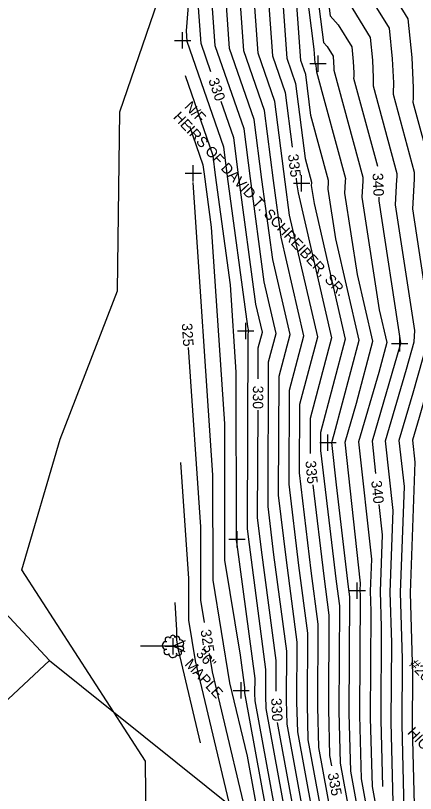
# Model space of a CAD drawing. Extents: x 487096 to 489566, y 221939 to 224454.
# Drawn here: x 488250.6 to 488373.2, y 222981.8 to 223219.9 of the extents above; entities that cross this region are included whole.
import ezdxf

# ---------------------------------------------------------------- set-up
doc = ezdxf.new("R2010")
doc.units = 0
for name, color, linetype in [('SV_CTRL_BM_INFO_BOX', 7, 'Continuous'), ('SV_ROWL_ROWL_TX', 7, 'Continuous'), ('SV_SURF_INDEX_CONTOUR', 7, 'Continuous'), ('SV_SURF_INTER_CONTOUR', 7, 'Continuous'), ('SV_SURF_SPOT', 7, 'Continuous'), ('SV_TREE_TREEVEG', 7, 'Continuous'), ('SV_TREE_TREEVEG_TX', 7, 'Continuous'), ('SV_UTOH_MISC_OH', 7, 'Continuous'), ('SV_UTOH_UTOH_TX', 7, 'Continuous'), ('SV_WATR_INWETF', 7, 'Continuous')]:
    doc.layers.add(name, color=color, linetype=linetype)

msp = doc.modelspace()

# ---------------------------------------------------------------- linework, layer by layer
at = {"layer": 'SV_CTRL_BM_INFO_BOX'}
msp.add_line((488260.98, 223022.49), (488394.91, 222915.38), dxfattribs=at)
msp.add_lwpolyline([(488175.2, 223114.48), (488260.98, 223022.49), (488234.03, 222997.36), (488148.26, 223089.35)], close=True, dxfattribs=at)
at = {"layer": 'SV_SURF_INDEX_CONTOUR'}
for points in [[(488310.47, 223202.71), (488307.47, 223211.35), (488306.48, 223225.22), (488310.84, 223279.98), (488309.25, 223288.25)], [(488325.23, 223265.13), (488329.34, 223207.61), (488333.25, 223196.36), (488335.38, 223179.67)], [(488342.28, 223256.77), (488347.01, 223219.79), (488349.5, 223217.08), (488353.65, 223210.35), (488354.1, 223205.9), (488354.27, 223202.43), (488354.27, 223202.11), (488354.27, 223201.89), (488354.26, 223201.45), (488354.26, 223201.23), (488354.25, 223200.78), (488361.53, 223173.86)], [(488324.97, 223108.74), (488325.01, 223118.17), (488326.28, 223122.95), (488324.29, 223131.57), (488319.04, 223170.36), (488317.49, 223182.52), (488313.62, 223193.65)], [(488336.6, 223170.15), (488336.78, 223168.73), (488337.2, 223165.67), (488347.45, 223121.22), (488340.91, 223096.6), (488340.87, 223085.82)], [(488361.98, 223164.27), (488361.92, 223163.16), (488368.63, 223119.72), (488368.62, 223119.55), (488368.5, 223119.11), (488359.9, 223089.58), (488360.97, 223079.74)], [(488308.53, 223034.09), (488307.4, 223040.95), (488307.36, 223063.37), (488303.66, 223118.32)], [(488330.45, 223013.12), (488330.49, 223022.52), (488325.99, 223056.4), (488324.81, 223066.24), (488324.94, 223099.14)], [(488341.7, 223076.26), (488345.07, 223048.28), (488346.65, 223036.4), (488346.5, 223007.64), (488346.86, 222993.42), (488347.45, 222990.23)], [(488362.01, 223070.2), (488363.02, 223060.95), (488362.4, 223043.57), (488362.71, 223032.73), (488362.56, 223004.23), (488363.08, 222983.89)], [(488328.45, 222940.22), (488324.17, 222963.52), (488311, 223019), (488310.08, 223024.61)], [(488344.86, 222918.34), (488344.39, 222924.14), (488343.22, 222936.46), (488330.92, 223003.53)]]:
    msp.add_lwpolyline(points, dxfattribs=at)
at = {"layer": 'SV_SURF_INTER_CONTOUR'}
for points in [[(488308.1, 223280.91), (488302.87, 223215.26), (488303.09, 223212.1), (488314.33, 223179.75), (488315.49, 223170.68), (488321.71, 223124.75), (488322.05, 223123.29), (488321.83, 223122.48), (488321.6, 223062.82), (488322.18, 223058.03), (488327.26, 223019.75), (488327.22, 223011.73), (488327.32, 223007.77), (488340.7, 222934.86), (488341.68, 222924.51), (488344.26, 222893.01), (488345.44, 222874.2), (488346.87, 222866.97)], [(488363.41, 222949.28), (488356.63, 222986.24), (488356.14, 223005.59), (488356.33, 223042.44), (488356.29, 223043.85), (488356.37, 223046.11), (488351.65, 223089.33), (488355.11, 223101.22), (488360.16, 223120.19), (488355.43, 223140.65), (488351.59, 223165.54), (488351.78, 223169.09), (488351.79, 223169.42), (488351.81, 223169.92), (488342.98, 223202.56), (488342.71, 223204.66), (488342.47, 223205.37), (488342.16, 223209.67), (488333.62, 223276.41)], [(488336.64, 223276.8), (488344.98, 223211.69), (488346.08, 223210.49), (488347.92, 223207.5), (488348.12, 223205.52), (488348.2, 223203.98), (488348.2, 223203.84), (488348.2, 223203.74), (488348.19, 223203.55), (488348.19, 223203.45), (488348.19, 223203.25), (488357.07, 223170.43), (488357.04, 223169.75), (488357.02, 223169.29), (488356.75, 223164.35), (488362.1, 223129.78), (488364.39, 223119.84), (488361.94, 223110.63), (488355.78, 223089.46), (488359.69, 223053.53), (488359.34, 223043.71), (488359.52, 223037.58), (488359.35, 223004.91), (488359.88, 222983.85), (488365.93, 222950.88)], [(488362.65, 222861.37), (488360.69, 222871.28), (488360.25, 222873.42), (488359.64, 222876.54), (488358.42, 222883.72), (488355.23, 222922.66), (488353.32, 222942.87), (488343.6, 222995.81), (488343.29, 223008.32), (488343.42, 223033.62), (488341.25, 223049.9), (488337.65, 223079.89), (488337.73, 223100.91), (488343.22, 223121.57), (488334.61, 223158.85), (488333.23, 223169.06), (488330.1, 223193.59), (488324.97, 223208.36), (488320.92, 223265.03)], [(488359.49, 222862.49), (488357.31, 222873.5), (488357.06, 222874.76), (488356.7, 222876.6), (488355.97, 222880.83), (488352.52, 222923.03), (488350.79, 222941.27), (488340.35, 222998.2), (488340.07, 223009), (488340.19, 223030.85), (488337.44, 223051.53), (488334.44, 223076.48), (488334.55, 223105.23), (488338.98, 223121.91), (488332.03, 223152.03), (488329.68, 223169.38), (488326.95, 223190.82), (488320.59, 223209.11), (488317.31, 223255.08)], [(488330.36, 223253.85), (488333.72, 223206.86), (488336.41, 223199.13), (488339.34, 223176.14), (488341.3, 223168.89), (488341.3, 223168.78), (488341.3, 223168.7), (488341.25, 223167.91), (488342.11, 223162.38), (488351.69, 223120.88), (488344.09, 223092.29), (488344.07, 223086.72), (488348.88, 223046.65), (488349.88, 223039.17), (488349.71, 223006.96), (488350.12, 222991.02), (488358.36, 222946.07), (488360.64, 222921.92), (488363.3, 222889.49), (488365.53, 222876.42), (488366.64, 222870.73), (488367.44, 222866.83), (488368.96, 222859.13)], [(488356.34, 222863.61), (488353.94, 222875.72), (488353.86, 222876.1), (488353.75, 222876.66), (488353.53, 222877.95), (488349.81, 222923.4), (488348.27, 222939.67), (488337.09, 223000.59), (488336.86, 223009.68), (488336.96, 223028.07), (488333.62, 223053.15), (488331.23, 223073.06), (488331.37, 223109.54), (488334.75, 223122.26), (488329.45, 223145.21), (488326.14, 223169.71), (488323.79, 223188.06), (488316.22, 223209.85), (488313.7, 223245.12)], [(488359.77, 223236.87), (488370.82, 223218.92), (488372.04, 223207.04), (488372.48, 223197.79), (488372.48, 223196.92), (488372.48, 223196.34), (488372.46, 223195.16), (488372.45, 223194.58), (488372.43, 223193.39), (488378.09, 223172.49), (488378.03, 223171.04), (488377.99, 223170.07), (488377.41, 223159.59), (488381.85, 223130.93), (488381.2, 223120.99), (488374.29, 223096.91), (488372.27, 223089.95), (488373, 223083.2), (488371.57, 223043.15), (488372.28, 223018.17), (488372.2, 223002.18), (488372.91, 222974.28)], [(488353.18, 222864.73), (488350.92, 222876.14), (488350.66, 222880.27), (488347.1, 222923.77), (488345.75, 222938.07), (488333.84, 223002.98), (488333.65, 223010.37), (488333.72, 223025.3), (488329.81, 223054.78), (488328.02, 223069.65), (488328.19, 223113.86), (488330.51, 223122.6), (488326.87, 223138.39), (488322.59, 223170.03), (488320.64, 223185.29), (488311.84, 223210.6), (488310.09, 223235.17)], [(488372.12, 222858.01), (488370.81, 222864.61), (488369.84, 222869.39), (488368.47, 222876.36), (488365.75, 222892.37), (488363.35, 222921.55), (488360.89, 222947.67), (488353.37, 222988.63), (488352.92, 223006.27), (488353.11, 223041.95), (488352.7, 223045.03), (488348.94, 223076.26), (488347.53, 223089.21), (488348.29, 223091.81), (488355.92, 223120.53), (488348.77, 223151.52), (488346.42, 223166.72), (488346.54, 223168.9), (488346.55, 223169.1), (488346.56, 223169.4), (488341.16, 223189.35), (488339.56, 223201.89), (488338.09, 223206.12), (488336.26, 223231.76)], [(488356.35, 223230.28), (488365.1, 223216.06), (488366.06, 223206.66), (488366.41, 223199.34), (488366.41, 223198.65), (488366.41, 223198.19), (488366.4, 223197.26), (488366.39, 223196.79), (488366.37, 223195.86), (488372.83, 223171.98), (488372.78, 223170.72), (488372.75, 223169.88), (488372.25, 223160.78), (488377.44, 223127.2), (488377.01, 223120.51), (488372.36, 223104.31), (488368.14, 223089.82), (488369.68, 223075.78), (488368.51, 223043.29), (488369.09, 223023.02), (488368.99, 223002.86), (488369.65, 222976.67)], [(488366.4, 222979.07), (488365.77, 223003.54), (488365.9, 223027.88), (488365.46, 223043.43), (488366.35, 223068.37), (488364.02, 223089.7), (488370.43, 223111.71), (488372.81, 223120.03), (488373.04, 223123.46), (488367.08, 223161.97), (488367.51, 223169.68), (488367.54, 223170.4), (488367.58, 223171.46), (488360.31, 223198.32), (488360.32, 223199.01), (488360.33, 223199.36), (488360.34, 223200.04), (488360.34, 223200.38), (488360.34, 223200.89), (488360.08, 223206.28), (488359.37, 223213.21), (488352.93, 223223.68)], [(488343.71, 222868.09), (488342.69, 222873.22), (488341.06, 222899.38), (488338.97, 222924.88), (488338.18, 222933.26), (488324.07, 223010.16), (488324.01, 223012.41), (488324.03, 223016.97), (488318.59, 223057.97), (488318.37, 223059.28), (488318.28, 223110.78), (488316.49, 223137.44), (488311.94, 223171.01), (488311.18, 223176.99), (488302.67, 223201.46)], [(488303.92, 223186.04), (488308.03, 223174.22), (488308.39, 223171.33), (488310.59, 223155.12), (488314.64, 223094.97), (488314.71, 223053.17), (488319.49, 223024.11), (488320.8, 223014.2), (488320.8, 223013.1), (488320.81, 223012.55), (488335.65, 222931.66), (488336.26, 222925.25), (488337.86, 222905.75), (488339.95, 222872.25), (488340.55, 222869.21)], [(488304.96, 223168.81), (488311, 223079.17), (488311.05, 223047.06), (488316.22, 223015.62), (488321.56, 222993.14), (488333.13, 222930.06), (488333.55, 222925.62), (488334.66, 222912.11), (488337.21, 222871.28), (488337.4, 222870.33)], [(488328.64, 222918.67), (488328.26, 222924.85), (488328.13, 222926.36), (488328.08, 222926.86), (488326.79, 222933.91), (488305.79, 223022.38), (488303.74, 223034.84), (488303.72, 223047.56), (488301.33, 223083.09)], [(488307.35, 222997.22), (488300.57, 223025.75), (488300.08, 223028.73), (488300.08, 223031.76), (488299.51, 223040.23)]]:
    msp.add_lwpolyline(points, dxfattribs=at)
at = {"layer": 'SV_SURF_SPOT'}
for p, q in [((488301.8, 223209.82), (488301.8, 223214.82)), ((488299.3, 223212.32), (488304.3, 223212.32)), ((488301.8, 223212.32), (488301.8, 223212.32)), ((488343.35, 223202.72), (488343.35, 223207.72)), ((488340.85, 223205.22), (488345.85, 223205.22)), ((488343.35, 223205.22), (488343.35, 223205.22)), ((488305.08, 223169.13), (488305.08, 223174.14)), ((488302.58, 223171.63), (488307.58, 223171.63)), ((488305.08, 223171.63), (488305.08, 223171.63)), ((488338.3, 223166.09), (488338.3, 223171.09)), ((488335.8, 223168.59), (488340.8, 223168.59)), ((488338.3, 223168.59), (488338.3, 223168.59)), ((488321.18, 223120.86), (488321.18, 223125.86)), ((488318.68, 223123.36), (488323.68, 223123.36)), ((488321.18, 223123.36), (488321.18, 223123.36)), ((488368.39, 223117.02), (488368.39, 223122.02)), ((488365.89, 223119.52), (488370.89, 223119.52)), ((488368.39, 223119.52), (488368.39, 223119.52)), ((488346.38, 223086.68), (488346.38, 223091.68)), ((488343.88, 223089.18), (488348.88, 223089.18)), ((488346.38, 223089.18), (488346.38, 223089.18)), ((488318.54, 223057.07), (488318.54, 223062.07)), ((488316.04, 223059.57), (488321.04, 223059.57)), ((488318.54, 223059.57), (488318.54, 223059.57)), ((488355.37, 223041.39), (488355.37, 223046.39)), ((488352.87, 223043.89), (488357.87, 223043.89)), ((488355.37, 223043.89), (488355.37, 223043.89)), ((488298.94, 223024.31), (488298.94, 223029.31)), ((488296.44, 223026.81), (488301.44, 223026.81)), ((488298.94, 223026.81), (488298.94, 223026.81)), ((488319.77, 223010.81), (488319.77, 223015.82)), ((488317.27, 223013.31), (488322.27, 223013.31)), ((488319.77, 223013.31), (488319.77, 223013.31))]:
    msp.add_line(p, q, dxfattribs=at)
at = {"layer": 'SV_TREE_TREEVEG'}
msp.add_line((488298.94, 223026.81), (488298.94, 223026.81), dxfattribs=at)
for centre, radius, start, end in [((488297.33, 223028.78), 0.874, 35.9933, 211.459), ((488298.83, 223029.46), 0.75, 23.2911, 192.3579), ((488300.14, 223029.05), 0.85, 345.5308, 152.7093), ((488301.1, 223027.69), 1.06, 294.1859, 111.1082), ((488296.74, 223027.06), 1.17, 79.3292, 279.9889), ((488297.02, 223025.21), 0.922, 137.0157, 304.5501)]:
    msp.add_arc(centre, radius, start, end, dxfattribs=at)
for centre, major_axis, ratio, start_param, end_param in [((488301.39, 223026.05), (0.822, -0.013), 0.901056, 4.216583, 7.444153), ((488298.81, 223024.48), (-1.2, 0.16), 0.902156, 0, 3.5401), ((488300.66, 223024.84), (0.08, -0.798), 0.999752, 5.391582, 8.241319)]:
    msp.add_ellipse(centre, major_axis=major_axis, ratio=ratio, start_param=start_param, end_param=end_param, dxfattribs=at)
at = {"layer": 'SV_UTOH_MISC_OH'}
for p, q in [((488298.94, 223026.81), (488288.94, 223026.81)), ((488302.56, 223028.5), (488298.94, 223026.81)), ((488302.56, 223025.12), (488298.94, 223026.81))]:
    msp.add_line(p, q, dxfattribs=at)
at = {"layer": 'SV_WATR_INWETF'}
for points in [[(488252.55, 223050.25), (488264.25, 223090.23), (488281.91, 223135.61), (488282.57, 223190.44), (488295.5, 223227.97), (488308.75, 223255.15), (488305.2, 223268.34), (488289.17, 223314.01), (488298.4, 223369.86), (488304.63, 223422.7), (488301.31, 223432.19)], [(488317.45, 222831.55), (488289.87, 222898.26), (488291.06, 222931.37), (488290.46, 222991.69), (488252.55, 223050.25)]]:
    msp.add_lwpolyline(points, dxfattribs=at)

# ---------------------------------------------------------------- texts
at = {"layer": 'SV_ROWL_ROWL_TX'}
for s, p in [('N/F', (488302.19, 223191.87)), ('HEIRS OF DAVID T. SCHREIBER, SR.', (488298.75, 223188.67))]:
    msp.add_text(s, height=3.2, rotation=313, dxfattribs=at).set_placement(p)
at = {"layer": 'SV_SURF_INDEX_CONTOUR'}
for s, rotation, p in [('330', 289.1629, (488309.66, 223200.16)), ('335', 277.2743, (488334.07, 223177.34)), ('340', 272.6202, (488360.04, 223171.65)), ('325', 273.8555, (488301.56, 223125.64)), ('330', 269.7783, (488323.37, 223106.6)), ('335', 275.0071, (488339.46, 223083.54)), ('340', 276.2232, (488359.61, 223077.43)), ('325', 279.329, (488307.29, 223031.71)), ('330', 272.809, (488328.95, 223010.9)), ('335', 280.3979, (488346.26, 222987.82))]:
    msp.add_text(s, height=3.2, rotation=rotation, dxfattribs=at).set_placement(p)
at = {"layer": 'SV_TREE_TREEVEG_TX'}
for s, p in [('36"', (488305.72, 223024.38)), ('MAPLE', (488302.28, 223021.18)), ('HICKORY', (488370.52, 223000.24))]:
    msp.add_text(s, height=3.2, rotation=313.0386, dxfattribs=at).set_placement(p)
at = {"layer": 'SV_UTOH_UTOH_TX'}
msp.add_text('#20829', height=3.2, rotation=313.0386, dxfattribs=at).set_placement((488371.04, 223021.07))

doc.saveas('drawing.dxf')
